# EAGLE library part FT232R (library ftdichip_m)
Source: http://www.ftdichip.com/Documents/DataSheets/DS_FT232R_v104.pdf
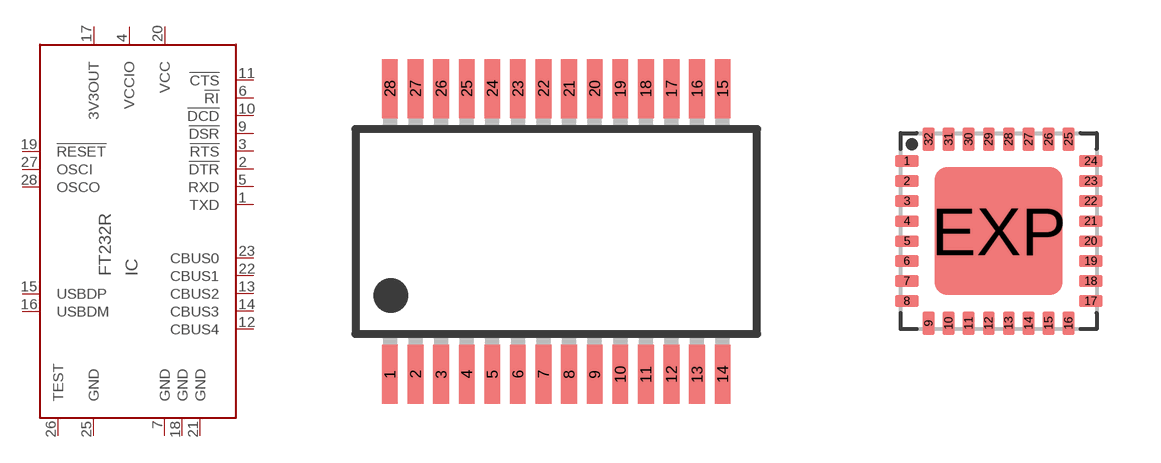
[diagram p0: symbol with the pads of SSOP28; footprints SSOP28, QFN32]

Designator prefix IC

## FT232RL (MPN: FT232RL; OC_FARNELL: 1146032; OC_NEWARK: 91K9918)  [SSOP28]
1  TXD  out
2  !DTR  out
3  !RTS  out
4  VCCIO  pwr
5  RXD  in
6  !RI  in
7  GND  pwr
9  !DSR  in
10  !DCD  in
11  !CTS  in
12  CBUS4
13  CBUS2
14  CBUS3
15  USBDP
16  USBDM
17  3V3OUT  out
18  GND  pwr
19  !RESET  in
20  VCC  pwr
21  GND  pwr
22  CBUS1
23  CBUS0
25  GND  pwr
26  TEST  in
27  OSCI  in
28  OSCO  out

## FT232RQ (MPN: FT232RQ; OC_FARNELL: 1146033; OC_NEWARK: 91K9919)  [QFN32]
1  VCCIO  pwr
2  RXD  in
3  !RI  in
4  GND  pwr
6  !DSR  in
7  !DCD  in
8  !CTS  in
9  CBUS4
10  CBUS2
11  CBUS3
14  USBDP
15  USBDM
16  3V3OUT  out
17  GND  pwr
18  !RESET  in
19  VCC  pwr
20  GND  pwr
21  CBUS1
22  CBUS0
24  GND  pwr
26  TEST  in
27  OSCI  in
28  OSCO  out
30  TXD  out
31  !DTR  out
32  !RTS  out

## Footprint SSOP28 (pad centres in mm)
Shrink Small Outline Package SSOP-28 http://www.ftdichip.com/Documents/DataSheets/DS_FT232R_v104.pdf
smd 0.4 x 1.5: 1 -4.225,-3.625; 2 -3.575,-3.625; 3 -2.925,-3.625; 4 -2.275,-3.625; 5 -1.625,-3.625; 6 -0.975,-3.625; 7 -0.325,-3.625; 8 0.325,-3.625; 9 0.975,-3.625; 10 1.625,-3.625; 11 2.275,-3.625; 12 2.925,-3.625; 13 3.575,-3.625; 14 4.225,-3.625; 15 4.225,3.625; 16 3.575,3.625; 17 2.925,3.625; 18 2.275,3.625; 19 1.625,3.625; 20 0.975,3.625; 21 0.325,3.625; 22 -0.325,3.625; 23 -0.975,3.625; 24 -1.625,3.625; 25 -2.275,3.625; 26 -2.925,3.625; 27 -3.575,3.625; 28 -4.225,3.625

## Footprint QFN32 (pad centres in mm)
QFN 32 Source: http://www.ftdichip.com/Documents/DataSheets/DS_FT232R_v104.pdf
smd 0.6 x 0.3: 1 -2.3,1.75; 2 -2.3,1.25; 3 -2.3,0.75; 4 -2.3,0.25; 5 -2.3,-0.25; 6 -2.3,-0.75; 7 -2.3,-1.25; 8 -2.3,-1.75; 17 2.3,-1.75; 18 2.3,-1.25; 19 2.3,-0.75; 20 2.3,-0.25; 21 2.3,0.25; 22 2.3,0.75; 23 2.3,1.25; 24 2.3,1.75
smd 0.3 x 0.6: 9 -1.75,-2.3; 10 -1.25,-2.3; 11 -0.75,-2.3; 12 -0.25,-2.3; 13 0.25,-2.3; 14 0.75,-2.3; 15 1.25,-2.3; 16 1.75,-2.3; 25 1.75,2.3; 26 1.25,2.3; 27 0.75,2.3; 28 0.25,2.3; 29 -0.25,2.3; 30 -0.75,2.3; 31 -1.25,2.3; 32 -1.75,2.3
smd 3.2 x 3.2: EXP 0,0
